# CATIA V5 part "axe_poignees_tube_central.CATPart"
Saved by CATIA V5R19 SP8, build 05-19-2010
Part number: axe_poignees_tube_central
Bounding box of the stored display mesh (mm): x 0 to 150, y -5 to 5, z -5 to 5
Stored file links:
  U:\Thinkmotion\Assemblage final\axe_poignees_tube_central.CATPart
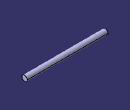
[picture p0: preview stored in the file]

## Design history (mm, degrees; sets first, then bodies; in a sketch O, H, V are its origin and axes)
Body1 (main body)
  Sketch1 on yz-plane, origin (0, 0, 0), H (0, 1, 0), V (0, 0, 1)
    circle A1 centre (0, 0) radius 5
  Pad1: profile Sketch1, direction (1, 0, 0), length 150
